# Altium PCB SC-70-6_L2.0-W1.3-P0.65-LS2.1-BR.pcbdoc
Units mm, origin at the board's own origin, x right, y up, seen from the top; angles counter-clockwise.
Board outline 15.6 x 15.19 mm, 2 copper layers (Top Layer, Bottom Layer), stack 0 mm thick; 1 components, 0 nets, 6 pads, 0 vias.
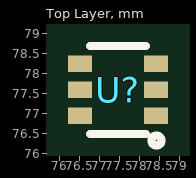
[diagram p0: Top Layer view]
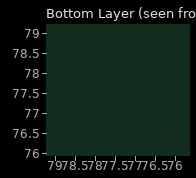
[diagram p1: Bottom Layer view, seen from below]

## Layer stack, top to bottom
Top Layer: signal copper (thickness not stored)
Bottom Layer: signal copper (thickness not stored)

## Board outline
85.449,69.85 69.85,69.85 69.85,85.043 85.449,85.043

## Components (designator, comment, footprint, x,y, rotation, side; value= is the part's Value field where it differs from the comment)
U? "" SC-70-6_L2.0-W1.3-P0.65-LS2.1-BR 77.45,77.593 r0 top

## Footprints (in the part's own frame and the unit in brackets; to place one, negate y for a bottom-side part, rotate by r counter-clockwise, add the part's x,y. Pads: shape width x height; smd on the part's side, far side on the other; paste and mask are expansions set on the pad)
SC-70-6_L2.0-W1.3-P0.65-LS2.1-BR [mm]
  rect 0.6x0.42 smd: 1(0.95,-0.65) 2(0.95,0) 3(0.95,0.65) 4(-0.95,0.65) 5(-0.95,0) 6(-0.95,-0.65)
  silkscreen extent -0.7,-1.39 1.09,1.1

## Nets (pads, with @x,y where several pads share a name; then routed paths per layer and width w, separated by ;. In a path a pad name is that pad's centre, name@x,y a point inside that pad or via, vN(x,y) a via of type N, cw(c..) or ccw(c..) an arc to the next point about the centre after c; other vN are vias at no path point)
pads on no net: U?.1 U?.2 U?.3 U?.4 U?.5 U?.6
